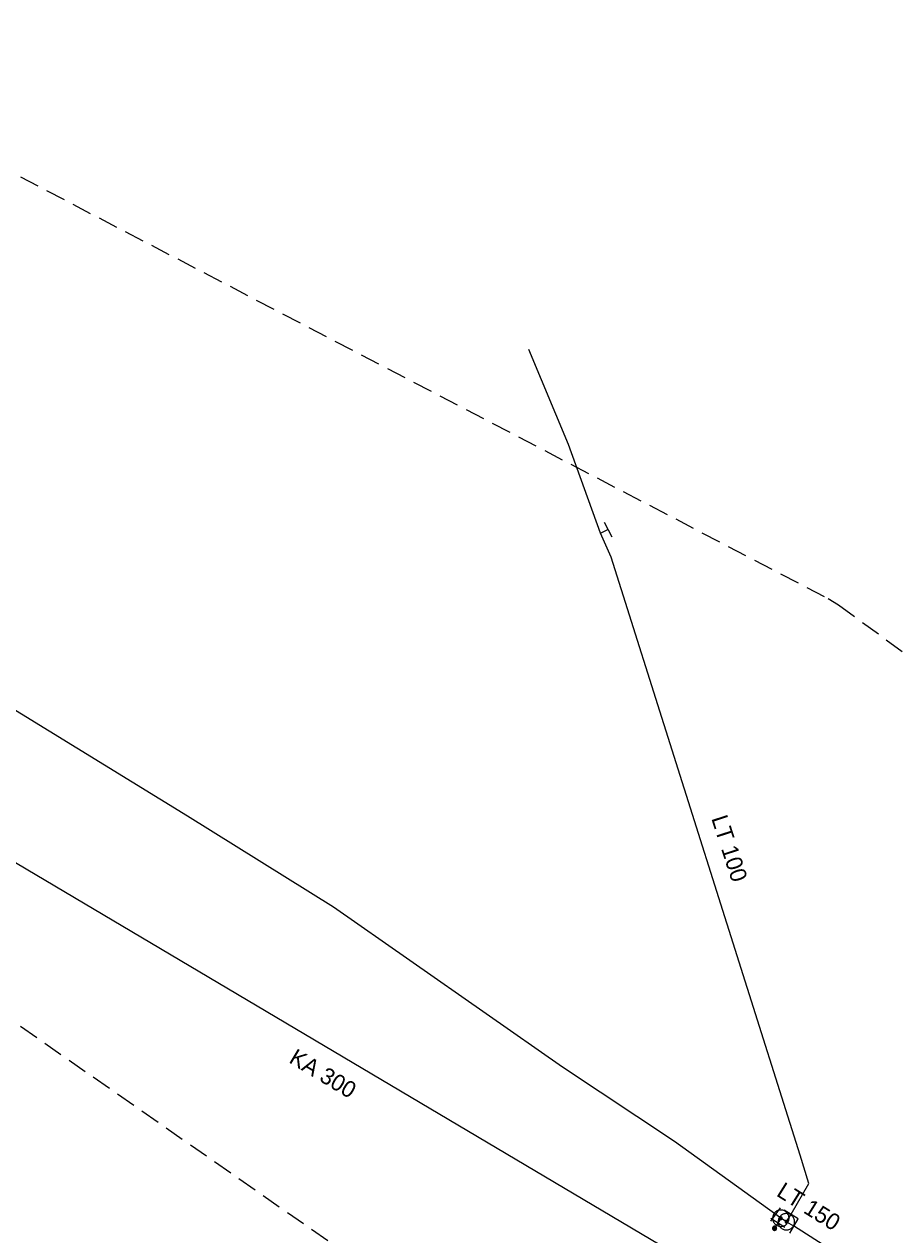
# Model space of a CAD drawing. Extents: x -749365 to -748625, y -965388 to -964881.
# Drawn here: x -748893.2 to -748840.2, y -965189.7 to -965116 of the extents above; entities that cross this region are included whole.
import ezdxf

# ---------------------------------------------------------------- set-up
doc = ezdxf.new("R2010")
doc.units = 0
doc.header["$LTSCALE"] = 0.4
doc.linetypes.add('MEDIUM_DASHED', pattern=[4.5, 3, -1.5])
for name, color, linetype, lineweight in [('1', 7, 'MEDIUM_DASHED', 25), ('14', 7, 'Continuous', 13), ('17', 7, 'Continuous', 25), ('34', 7, 'Continuous', 13), ('47', 7, 'Continuous', 13), ('9', 7, 'Continuous', 13)]:
    doc.layers.add(name, color=color, linetype=linetype, lineweight=lineweight)

msp = doc.modelspace()

# ---------------------------------------------------------------- linework, layer by layer
at = {"layer": '1'}
for points in [[(-748747.771, -965278.626), (-748913.896, -965162.751), (-749358.2, -964911.234)], [(-749094.514, -965020.387), (-748844.275, -965150.977), (-748843.645, -965151.367), (-748721.639, -965240.188)]]:
    msp.add_lwpolyline(points, dxfattribs=at)
at = {"layer": '14'}
for p, q in [((-748858.127, -965147.005), (-748857.683, -965146.774)), ((-748847.155, -965188.686), (-748847.466, -965188.465)), ((-748846.815, -965188.899), (-748846.526, -965188.443)), ((-748847.344, -965188.98), (-748847.536, -965189.298)), ((-748847.155, -965188.686), (-748847.344, -965188.98)), ((-748846.815, -965188.899), (-748846.378, -965189.157))]:
    msp.add_line(p, q, dxfattribs=at)
at = {"layer": '14', "lineweight": 25}
msp.add_line((-748900.66, -965162.96), (-748846.48, -965195.039), dxfattribs=at)
at = {"layer": '14'}
msp.add_lwpolyline([(-748846.815, -965188.899), (-748847.155, -965188.686), (-748847.466, -965188.465)], dxfattribs=at)
at = {"layer": '17'}
msp.add_line((-748844.578, -965190.3), (-748846.378, -965189.157), dxfattribs=at)
for points in [[(-748847.466, -965188.465), (-748853.619, -965184.024), (-748860.449, -965179.484), (-748874.395, -965169.75), (-748883.27, -965164.229), (-748898.443, -965154.905), (-748902.451, -965152.696), (-748912.348, -965147.052), (-748917.379, -965144.189), (-748932.225, -965135.764), (-748939.709, -965131.511), (-748953.41, -965123.331), (-748968.378, -965114.457), (-748985.31, -965104.682), (-749003.06, -965094.212), (-749006.577, -965092.085), (-749027.381, -965079.535)], [(-748846.526, -965188.443), (-748845.458, -965186.574), (-748845.969, -965184.84), (-748857.478, -965148.464), (-748858.127, -965147.005), (-748860.072, -965141.6), (-748862.491, -965135.831)]]:
    msp.add_lwpolyline(points, dxfattribs=at)
at = {"layer": '34'}
for p, q in [((-748857.913, -965146.33), (-748857.453, -965147.217)), ((-748847.755, -965188.872), (-748847.175, -965188.058)), ((-748846.949, -965188.176), (-748846.103, -965188.71)), ((-748846.922, -965189.249), (-748847.764, -965188.709)), ((-748846.124, -965188.725), (-748846.632, -965189.587))]:
    msp.add_line(p, q, dxfattribs=at)
at = {"layer": '47'}
for points in [[(-748847.578, -965188.42), (-748847.603, -965188.466), (-748847.624, -965188.514), (-748847.639, -965188.564), (-748847.65, -965188.615), (-748847.654, -965188.668), (-748847.653, -965188.721), (-748847.646, -965188.772), (-748847.634, -965188.823), (-748847.618, -965188.872), (-748847.596, -965188.92), (-748847.569, -965188.965), (-748847.537, -965189.007), (-748847.502, -965189.045), (-748847.462, -965189.079), (-748847.42, -965189.109), (-748847.374, -965189.134), (-748847.326, -965189.155), (-748847.275, -965189.17), (-748847.225, -965189.181), (-748847.172, -965189.185), (-748847.119, -965189.184), (-748847.067, -965189.178), (-748847.016, -965189.166), (-748846.967, -965189.15), (-748846.92, -965189.127), (-748846.875, -965189.1), (-748846.833, -965189.068), (-748846.795, -965189.033), (-748846.761, -965188.993), (-748846.731, -965188.951), (-748846.706, -965188.905), (-748846.685, -965188.857), (-748846.669, -965188.807), (-748846.659, -965188.756), (-748846.655, -965188.703), (-748846.655, -965188.651), (-748846.661, -965188.599), (-748846.673, -965188.548), (-748846.69, -965188.498), (-748846.713, -965188.451), (-748846.74, -965188.406), (-748846.771, -965188.364), (-748846.807, -965188.326), (-748846.847, -965188.292), (-748846.889, -965188.262), (-748846.935, -965188.237), (-748846.983, -965188.216), (-748847.033, -965188.2), (-748847.084, -965188.19), (-748847.137, -965188.186), (-748847.189, -965188.186), (-748847.24, -965188.193), (-748847.291, -965188.205), (-748847.341, -965188.222), (-748847.389, -965188.244), (-748847.434, -965188.271), (-748847.475, -965188.302), (-748847.514, -965188.338), (-748847.548, -965188.378)], [(-748846.384, -965189.152), (-748846.36, -965189.106), (-748846.34, -965189.057), (-748846.327, -965189.007), (-748846.318, -965188.956), (-748846.315, -965188.903), (-748846.317, -965188.85), (-748846.325, -965188.799), (-748846.338, -965188.748), (-748846.356, -965188.7), (-748846.379, -965188.652), (-748846.408, -965188.608), (-748846.441, -965188.567), (-748846.477, -965188.53), (-748846.517, -965188.497), (-748846.561, -965188.468), (-748846.607, -965188.444), (-748846.656, -965188.424), (-748846.707, -965188.411), (-748846.757, -965188.402), (-748846.81, -965188.399), (-748846.863, -965188.401), (-748846.915, -965188.409), (-748846.965, -965188.422), (-748847.014, -965188.44), (-748847.061, -965188.463), (-748847.105, -965188.492), (-748847.146, -965188.524), (-748847.183, -965188.561), (-748847.216, -965188.601), (-748847.245, -965188.645), (-748847.269, -965188.691), (-748847.289, -965188.74), (-748847.303, -965188.79), (-748847.311, -965188.841), (-748847.314, -965188.894), (-748847.313, -965188.946), (-748847.305, -965188.998), (-748847.292, -965189.049), (-748847.273, -965189.098), (-748847.25, -965189.145), (-748847.221, -965189.189), (-748847.19, -965189.23), (-748847.152, -965189.267), (-748847.112, -965189.3), (-748847.068, -965189.329), (-748847.022, -965189.353), (-748846.973, -965189.373), (-748846.923, -965189.387), (-748846.872, -965189.395), (-748846.819, -965189.398), (-748846.767, -965189.397), (-748846.716, -965189.389), (-748846.665, -965189.375), (-748846.616, -965189.357), (-748846.568, -965189.334), (-748846.524, -965189.305), (-748846.484, -965189.273), (-748846.446, -965189.236), (-748846.413, -965189.196)], [(-748847.224, -965188.642), (-748847.229, -965188.65), (-748847.231, -965188.657), (-748847.234, -965188.665), (-748847.236, -965188.674), (-748847.236, -965188.683), (-748847.236, -965188.691), (-748847.235, -965188.7), (-748847.233, -965188.708), (-748847.23, -965188.716), (-748847.227, -965188.724), (-748847.222, -965188.732), (-748847.217, -965188.738), (-748847.211, -965188.744), (-748847.206, -965188.75), (-748847.198, -965188.755), (-748847.19, -965188.76), (-748847.183, -965188.762), (-748847.175, -965188.765), (-748847.166, -965188.767), (-748847.157, -965188.767), (-748847.149, -965188.767), (-748847.14, -965188.766), (-748847.132, -965188.764), (-748847.123, -965188.762), (-748847.116, -965188.758), (-748847.108, -965188.753), (-748847.102, -965188.748), (-748847.096, -965188.742), (-748847.09, -965188.737), (-748847.085, -965188.729), (-748847.08, -965188.721), (-748847.078, -965188.714), (-748847.075, -965188.706), (-748847.073, -965188.697), (-748847.073, -965188.688), (-748847.072, -965188.68), (-748847.074, -965188.671), (-748847.076, -965188.663), (-748847.078, -965188.654), (-748847.082, -965188.647), (-748847.087, -965188.639), (-748847.092, -965188.633), (-748847.098, -965188.627), (-748847.103, -965188.621), (-748847.111, -965188.616), (-748847.119, -965188.611), (-748847.126, -965188.609), (-748847.134, -965188.606), (-748847.143, -965188.604), (-748847.152, -965188.604), (-748847.16, -965188.603), (-748847.169, -965188.605), (-748847.177, -965188.607), (-748847.185, -965188.61), (-748847.193, -965188.613), (-748847.201, -965188.618), (-748847.207, -965188.623), (-748847.213, -965188.629), (-748847.219, -965188.634)], [(-748846.744, -965188.94), (-748846.739, -965188.932), (-748846.737, -965188.924), (-748846.735, -965188.917), (-748846.733, -965188.908), (-748846.733, -965188.899), (-748846.733, -965188.891), (-748846.734, -965188.882), (-748846.736, -965188.874), (-748846.74, -965188.866), (-748846.743, -965188.858), (-748846.748, -965188.851), (-748846.753, -965188.844), (-748846.759, -965188.838), (-748846.765, -965188.832), (-748846.773, -965188.828), (-748846.781, -965188.823), (-748846.789, -965188.821), (-748846.796, -965188.819), (-748846.805, -965188.817), (-748846.814, -965188.817), (-748846.822, -965188.817), (-748846.831, -965188.818), (-748846.839, -965188.82), (-748846.848, -965188.823), (-748846.855, -965188.827), (-748846.862, -965188.832), (-748846.869, -965188.837), (-748846.875, -965188.843), (-748846.881, -965188.849), (-748846.885, -965188.857), (-748846.89, -965188.865), (-748846.892, -965188.873), (-748846.894, -965188.88), (-748846.896, -965188.889), (-748846.896, -965188.898), (-748846.897, -965188.906), (-748846.895, -965188.915), (-748846.893, -965188.923), (-748846.89, -965188.932), (-748846.886, -965188.939), (-748846.881, -965188.946), (-748846.876, -965188.953), (-748846.87, -965188.959), (-748846.864, -965188.965), (-748846.856, -965188.969), (-748846.848, -965188.974), (-748846.84, -965188.976), (-748846.833, -965188.978), (-748846.824, -965188.98), (-748846.815, -965188.98), (-748846.807, -965188.981), (-748846.798, -965188.979), (-748846.79, -965188.977), (-748846.782, -965188.973), (-748846.774, -965188.97), (-748846.767, -965188.965), (-748846.76, -965188.96), (-748846.754, -965188.954), (-748846.748, -965188.948)]]:
    msp.add_lwpolyline(points, close=True, dxfattribs=at)
at = {"layer": '9'}
for points in [[(-748847.662, -965189.298), (-748847.662, -965189.311), (-748847.659, -965189.324), (-748847.657, -965189.337), (-748847.652, -965189.349), (-748847.646, -965189.361), (-748847.639, -965189.372), (-748847.63, -965189.382), (-748847.62, -965189.392), (-748847.61, -965189.4), (-748847.6, -965189.407), (-748847.588, -965189.413), (-748847.576, -965189.418), (-748847.563, -965189.421), (-748847.549, -965189.423), (-748847.537, -965189.425), (-748847.524, -965189.424), (-748847.511, -965189.422), (-748847.498, -965189.419), (-748847.485, -965189.414), (-748847.473, -965189.408), (-748847.463, -965189.401), (-748847.453, -965189.393), (-748847.443, -965189.383), (-748847.434, -965189.373), (-748847.428, -965189.362), (-748847.422, -965189.35), (-748847.417, -965189.338), (-748847.414, -965189.325), (-748847.412, -965189.312), (-748847.409, -965189.299), (-748847.411, -965189.286), (-748847.413, -965189.273), (-748847.416, -965189.26), (-748847.421, -965189.248), (-748847.426, -965189.236), (-748847.434, -965189.225), (-748847.441, -965189.215), (-748847.451, -965189.205), (-748847.462, -965189.197), (-748847.473, -965189.19), (-748847.485, -965189.184), (-748847.497, -965189.179), (-748847.51, -965189.176), (-748847.522, -965189.174), (-748847.536, -965189.173), (-748847.549, -965189.173), (-748847.561, -965189.175), (-748847.575, -965189.178), (-748847.587, -965189.183), (-748847.598, -965189.189), (-748847.61, -965189.196), (-748847.62, -965189.204), (-748847.63, -965189.214), (-748847.637, -965189.224), (-748847.645, -965189.235), (-748847.651, -965189.247), (-748847.656, -965189.259), (-748847.659, -965189.272), (-748847.661, -965189.285)], [(-748847.642, -965189.298), (-748847.642, -965189.309), (-748847.641, -965189.32), (-748847.637, -965189.331), (-748847.634, -965189.341), (-748847.629, -965189.351), (-748847.623, -965189.36), (-748847.615, -965189.369), (-748847.608, -965189.377), (-748847.598, -965189.384), (-748847.59, -965189.39), (-748847.58, -965189.395), (-748847.57, -965189.399), (-748847.559, -965189.402), (-748847.548, -965189.405), (-748847.537, -965189.405), (-748847.526, -965189.405), (-748847.515, -965189.403), (-748847.504, -965189.4), (-748847.494, -965189.396), (-748847.483, -965189.391), (-748847.475, -965189.385), (-748847.466, -965189.378), (-748847.458, -965189.37), (-748847.451, -965189.361), (-748847.445, -965189.352), (-748847.44, -965189.342), (-748847.436, -965189.332), (-748847.433, -965189.321), (-748847.431, -965189.31), (-748847.429, -965189.299), (-748847.429, -965189.288), (-748847.431, -965189.277), (-748847.434, -965189.266), (-748847.439, -965189.256), (-748847.444, -965189.246), (-748847.45, -965189.237), (-748847.456, -965189.228), (-748847.465, -965189.22), (-748847.473, -965189.213), (-748847.483, -965189.207), (-748847.493, -965189.202), (-748847.502, -965189.198), (-748847.514, -965189.195), (-748847.524, -965189.193), (-748847.536, -965189.193), (-748847.547, -965189.192), (-748847.558, -965189.194), (-748847.569, -965189.197), (-748847.578, -965189.201), (-748847.588, -965189.206), (-748847.598, -965189.212), (-748847.607, -965189.219), (-748847.615, -965189.227), (-748847.622, -965189.236), (-748847.627, -965189.245), (-748847.632, -965189.255), (-748847.637, -965189.265), (-748847.64, -965189.276), (-748847.642, -965189.287)], [(-748847.623, -965189.298), (-748847.623, -965189.307), (-748847.622, -965189.316), (-748847.619, -965189.325), (-748847.615, -965189.333), (-748847.612, -965189.341), (-748847.607, -965189.349), (-748847.6, -965189.356), (-748847.595, -965189.362), (-748847.588, -965189.368), (-748847.58, -965189.373), (-748847.571, -965189.377), (-748847.564, -965189.38), (-748847.554, -965189.383), (-748847.546, -965189.384), (-748847.537, -965189.386), (-748847.527, -965189.385), (-748847.519, -965189.384), (-748847.51, -965189.381), (-748847.502, -965189.378), (-748847.494, -965189.374), (-748847.485, -965189.369), (-748847.478, -965189.363), (-748847.473, -965189.357), (-748847.467, -965189.35), (-748847.462, -965189.342), (-748847.458, -965189.334), (-748847.455, -965189.326), (-748847.451, -965189.317), (-748847.451, -965189.308), (-748847.448, -965189.299), (-748847.45, -965189.29), (-748847.451, -965189.281), (-748847.453, -965189.272), (-748847.456, -965189.264), (-748847.461, -965189.256), (-748847.466, -965189.248), (-748847.472, -965189.241), (-748847.478, -965189.235), (-748847.485, -965189.229), (-748847.493, -965189.224), (-748847.5, -965189.22), (-748847.509, -965189.217), (-748847.517, -965189.214), (-748847.527, -965189.213), (-748847.536, -965189.212), (-748847.544, -965189.212), (-748847.554, -965189.213), (-748847.563, -965189.216), (-748847.571, -965189.219), (-748847.578, -965189.223), (-748847.587, -965189.228), (-748847.593, -965189.234), (-748847.6, -965189.24), (-748847.605, -965189.247), (-748847.61, -965189.255), (-748847.615, -965189.263), (-748847.618, -965189.271), (-748847.62, -965189.28), (-748847.622, -965189.289)], [(-748847.603, -965189.298), (-748847.603, -965189.305), (-748847.602, -965189.312), (-748847.6, -965189.319), (-748847.598, -965189.325), (-748847.595, -965189.331), (-748847.591, -965189.337), (-748847.587, -965189.343), (-748847.581, -965189.348), (-748847.576, -965189.352), (-748847.57, -965189.356), (-748847.564, -965189.359), (-748847.558, -965189.362), (-748847.551, -965189.363), (-748847.544, -965189.366), (-748847.537, -965189.366), (-748847.529, -965189.366), (-748847.522, -965189.364), (-748847.516, -965189.363), (-748847.51, -965189.36), (-748847.502, -965189.357), (-748847.498, -965189.353), (-748847.492, -965189.349), (-748847.487, -965189.344), (-748847.483, -965189.338), (-748847.478, -965189.332), (-748847.475, -965189.326), (-748847.473, -965189.32), (-748847.471, -965189.313), (-748847.47, -965189.306), (-748847.468, -965189.299), (-748847.468, -965189.292), (-748847.47, -965189.285), (-748847.472, -965189.278), (-748847.475, -965189.272), (-748847.478, -965189.265), (-748847.482, -965189.26), (-748847.485, -965189.254), (-748847.49, -965189.249), (-748847.497, -965189.245), (-748847.502, -965189.241), (-748847.509, -965189.238), (-748847.515, -965189.235), (-748847.522, -965189.233), (-748847.529, -965189.232), (-748847.536, -965189.232), (-748847.543, -965189.232), (-748847.549, -965189.232), (-748847.556, -965189.234), (-748847.563, -965189.237), (-748847.569, -965189.24), (-748847.575, -965189.244), (-748847.581, -965189.248), (-748847.586, -965189.253), (-748847.59, -965189.259), (-748847.593, -965189.264), (-748847.597, -965189.271), (-748847.6, -965189.277), (-748847.6, -965189.284), (-748847.603, -965189.291)], [(-748847.583, -965189.298), (-748847.583, -965189.303), (-748847.583, -965189.308), (-748847.581, -965189.313), (-748847.58, -965189.317), (-748847.578, -965189.322), (-748847.575, -965189.326), (-748847.571, -965189.329), (-748847.568, -965189.333), (-748847.565, -965189.336), (-748847.561, -965189.339), (-748847.556, -965189.341), (-748847.551, -965189.343), (-748847.547, -965189.344), (-748847.542, -965189.346), (-748847.537, -965189.346), (-748847.532, -965189.346), (-748847.527, -965189.345), (-748847.522, -965189.344), (-748847.517, -965189.342), (-748847.512, -965189.34), (-748847.509, -965189.337), (-748847.505, -965189.334), (-748847.502, -965189.33), (-748847.499, -965189.327), (-748847.495, -965189.323), (-748847.494, -965189.318), (-748847.492, -965189.314), (-748847.49, -965189.309), (-748847.49, -965189.304), (-748847.489, -965189.299), (-748847.489, -965189.294), (-748847.49, -965189.289), (-748847.49, -965189.284), (-748847.493, -965189.28), (-748847.495, -965189.275), (-748847.498, -965189.271), (-748847.5, -965189.267), (-748847.504, -965189.264), (-748847.507, -965189.261), (-748847.512, -965189.258), (-748847.517, -965189.256), (-748847.521, -965189.254), (-748847.526, -965189.253), (-748847.531, -965189.252), (-748847.536, -965189.252), (-748847.541, -965189.252), (-748847.546, -965189.253), (-748847.551, -965189.253), (-748847.554, -965189.255), (-748847.559, -965189.257), (-748847.564, -965189.26), (-748847.566, -965189.263), (-748847.571, -965189.266), (-748847.573, -965189.27), (-748847.576, -965189.274), (-748847.578, -965189.279), (-748847.581, -965189.283), (-748847.581, -965189.288), (-748847.583, -965189.293)], [(-748847.563, -965189.298), (-748847.563, -965189.301), (-748847.564, -965189.304), (-748847.563, -965189.306), (-748847.561, -965189.309), (-748847.561, -965189.312), (-748847.559, -965189.314), (-748847.556, -965189.316), (-748847.554, -965189.318), (-748847.553, -965189.32), (-748847.551, -965189.322), (-748847.548, -965189.324), (-748847.544, -965189.325), (-748847.543, -965189.325), (-748847.539, -965189.326), (-748847.537, -965189.326), (-748847.534, -965189.326), (-748847.531, -965189.326), (-748847.527, -965189.325), (-748847.526, -965189.324), (-748847.522, -965189.323), (-748847.521, -965189.321), (-748847.517, -965189.319), (-748847.516, -965189.317), (-748847.515, -965189.315), (-748847.512, -965189.313), (-748847.512, -965189.31), (-748847.51, -965189.307), (-748847.51, -965189.305), (-748847.509, -965189.302), (-748847.507, -965189.299), (-748847.509, -965189.296), (-748847.509, -965189.293), (-748847.51, -965189.29), (-748847.511, -965189.288), (-748847.512, -965189.285), (-748847.514, -965189.283), (-748847.515, -965189.28), (-748847.517, -965189.278), (-748847.52, -965189.277), (-748847.522, -965189.275), (-748847.524, -965189.274), (-748847.527, -965189.273), (-748847.529, -965189.272), (-748847.532, -965189.272), (-748847.536, -965189.271), (-748847.539, -965189.272), (-748847.542, -965189.271), (-748847.544, -965189.273), (-748847.547, -965189.273), (-748847.549, -965189.274), (-748847.551, -965189.276), (-748847.554, -965189.277), (-748847.556, -965189.279), (-748847.558, -965189.282), (-748847.559, -965189.284), (-748847.561, -965189.287), (-748847.561, -965189.289), (-748847.563, -965189.292), (-748847.563, -965189.295)], [(-748847.544, -965189.298), (-748847.544, -965189.3), (-748847.544, -965189.3), (-748847.543, -965189.3), (-748847.543, -965189.302), (-748847.544, -965189.303), (-748847.542, -965189.303), (-748847.542, -965189.303), (-748847.542, -965189.305), (-748847.542, -965189.305), (-748847.541, -965189.306), (-748847.539, -965189.306), (-748847.539, -965189.306), (-748847.539, -965189.307), (-748847.537, -965189.307), (-748847.537, -965189.307), (-748847.536, -965189.307), (-748847.534, -965189.307), (-748847.534, -965189.306), (-748847.534, -965189.306), (-748847.532, -965189.306), (-748847.532, -965189.305), (-748847.532, -965189.305), (-748847.531, -965189.304), (-748847.531, -965189.304), (-748847.529, -965189.303), (-748847.529, -965189.302), (-748847.527, -965189.301), (-748847.527, -965189.301), (-748847.527, -965189.3), (-748847.527, -965189.299), (-748847.527, -965189.298), (-748847.527, -965189.297), (-748847.527, -965189.297), (-748847.529, -965189.296), (-748847.529, -965189.295), (-748847.529, -965189.294), (-748847.529, -965189.294), (-748847.531, -965189.293), (-748847.531, -965189.293), (-748847.532, -965189.292), (-748847.532, -965189.292), (-748847.534, -965189.291), (-748847.534, -965189.291), (-748847.534, -965189.291), (-748847.536, -965189.291), (-748847.537, -965189.291), (-748847.538, -965189.291), (-748847.538, -965189.291), (-748847.539, -965189.292), (-748847.539, -965189.291), (-748847.541, -965189.293), (-748847.541, -965189.293), (-748847.542, -965189.293), (-748847.542, -965189.293), (-748847.543, -965189.295), (-748847.543, -965189.296), (-748847.543, -965189.297), (-748847.544, -965189.297), (-748847.544, -965189.298)]]:
    msp.add_lwpolyline(points, close=True, dxfattribs=at)

# ---------------------------------------------------------------- texts
at = {"layer": '1'}
for s, rotation, p in [('LT 100', 288, (-748851.398, -965164.351)), ('KA 300', 329, (-748877.162, -965179.179)), ('LT 150', 328, (-748847.482, -965187.288))]:
    msp.add_text(s, height=1, rotation=rotation, dxfattribs=at).set_placement(p)

doc.saveas('drawing.dxf')
